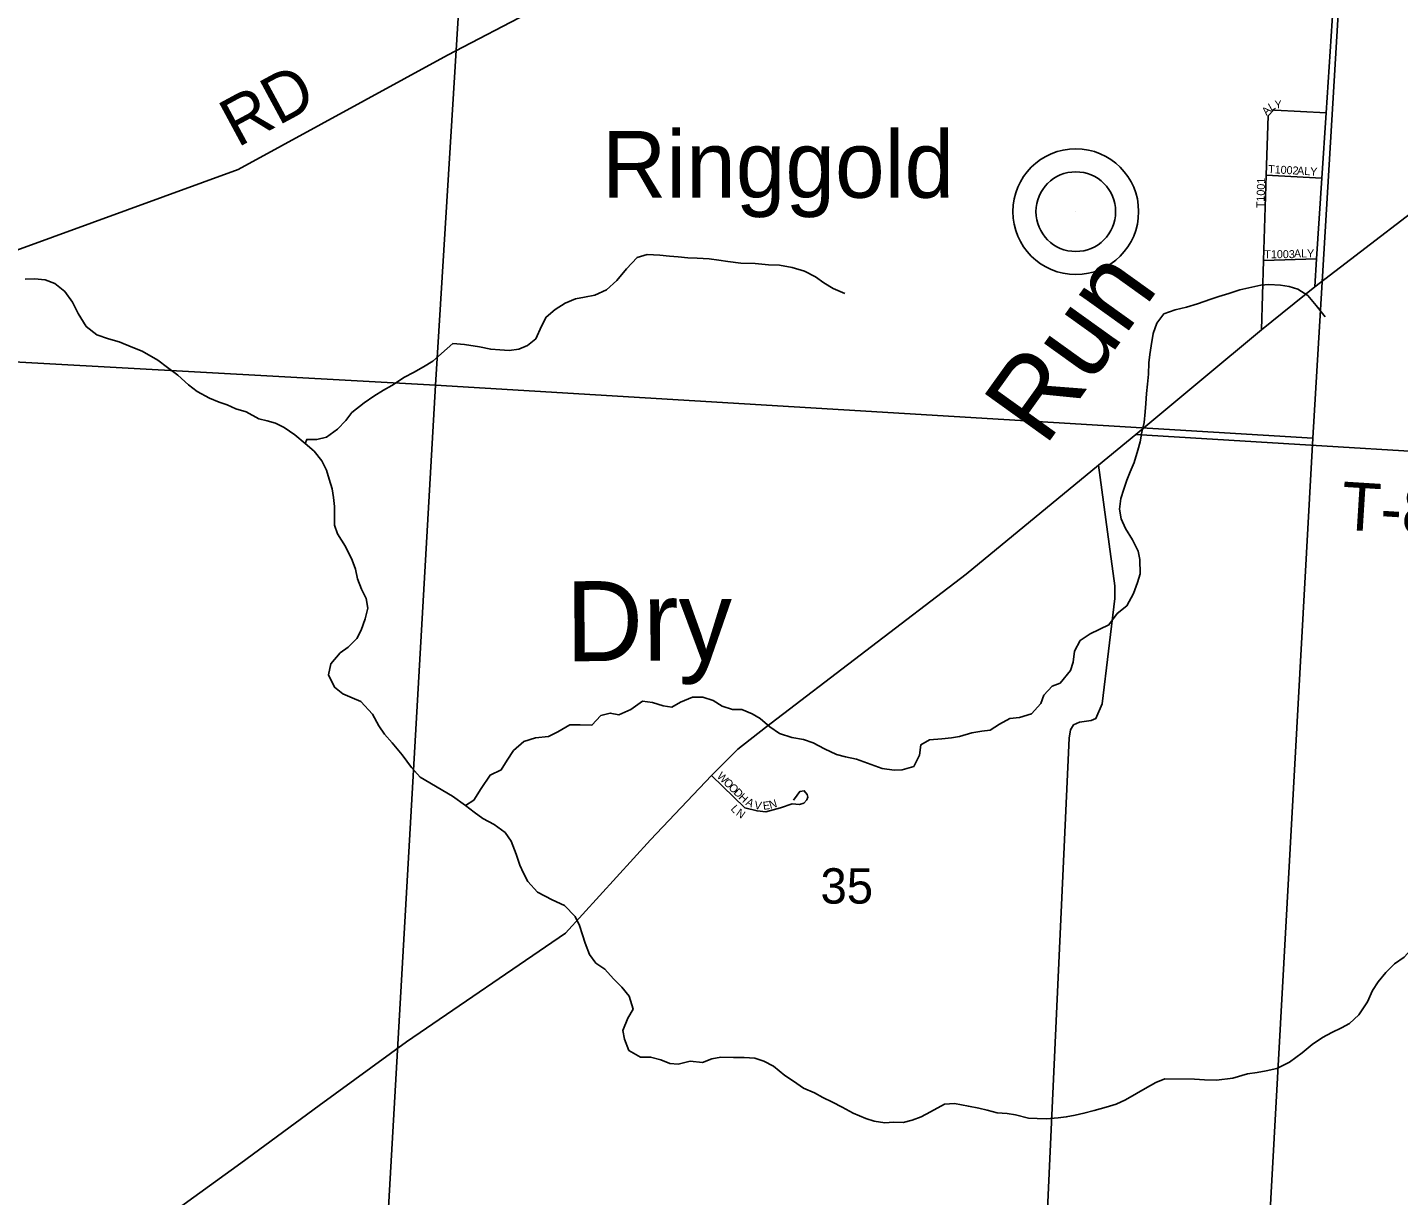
# Model space of a CAD drawing. Extents: x 1643459 to 2064572, y 425441 to 780708.
# Drawn here: x 1860299 to 1868868, y 602101 to 609399 of the extents above; entities that cross this region are included whole.
import ezdxf

# ---------------------------------------------------------------- set-up
doc = ezdxf.new("R2010")
doc.units = 0
for name, color, linetype in [('GE_P_Alignment_100_Curve_Data', 7, 'Continuous'), ('GM_X_Adjacent_County', 7, 'Continuous'), ('GM_X_County', 7, 'Continuous'), ('GM_X_Interchange_Ramps', 7, 'Continuous'), ('GM_X_Major_River', 7, 'Continuous'), ('GM_X_Major_River_Text', 7, 'Continuous'), ('GM_X_Minor_Lake', 7, 'Continuous'), ('GM_X_Rail_Line', 7, 'Continuous'), ('GM_X_State_Route', 7, 'Continuous'), ('GM_X_Township', 7, 'Continuous'), ('GM_X_Township_ROW', 7, 'Continuous'), ('GM_X_US_Route', 7, 'Continuous'), ('RD_X_Text', 7, 'Continuous')]:
    doc.layers.add(name, color=color, linetype=linetype)

msp = doc.modelspace()

# ---------------------------------------------------------------- linework, layer by layer
at = {"layer": 'GE_P_Alignment_100_Curve_Data'}
for radius in [392.8, 249]:
    msp.add_circle((1866850.6, 608248.3), radius, dxfattribs=at)
at = {"layer": 'GM_X_County'}
for points in [[(1868094, 608883.3), (1868093.8, 608883.4), (1868088.5, 608883.7), (1868052.2, 608847.9), (1868040.7, 608475.5), (1868024.2, 607942.7), (1868010.7, 607509)], [(1868415.4, 608866), (1868094, 608883.3)], [(1868040.7, 608475.5), (1868388.5, 608456.9)], [(1868024.2, 607942.7), (1868355.4, 607952.6)], [(1864574.9, 604724.7), (1864782.4, 604524.3), (1864859.2, 604503.9), (1864914.6, 604497.9), (1865004.6, 604523.2), (1865078.7, 604547.4), (1865124.7, 604544.9), (1865150.4, 604552.1), (1865170, 604572.6), (1865176.1, 604589.1), (1865172, 604607.6), (1865153.7, 604630.6), (1865125.8, 604625.1), (1865109.3, 604603.5), (1865086.7, 604570.6)]]:
    msp.add_lwpolyline(points, dxfattribs=at)
at = {"layer": 'GM_X_Major_River_Text'}
for points in [[(1857415.1, 607413.1), (1859119.2, 607332.8), (1859191.3, 607345), (1859211.3, 607367.1), (1859237.4, 607377.2), (1859289.5, 607369.3), (1859347.6, 607363.4), (1859403.7, 607387.6), (1859599.9, 607494.4), (1859984.2, 607762.1), (1860060.3, 607832.5), (1860154.2, 607953.1), (1860232.3, 608007.5), (1861616.3, 608512.3), (1862924.5, 609225.1), (1864011.6, 609793.8), (1868459.3, 609535.8)], [(1867226, 606856.6), (1873104.9, 606497.9), (1873820.9, 606443.6)], [(1866649.2, 601470.4), (1866810.2, 604959.6), (1866818.6, 605011.6), (1866836.9, 605041.5), (1866874.9, 605059.3), (1866946.9, 605068.7), (1866977, 605082.5), (1867015.6, 605172.3), (1867094.5, 605830.7), (1867095.1, 605910.8), (1867059.1, 606171.5), (1866992.9, 606664.6)]]:
    msp.add_lwpolyline(points, dxfattribs=at)
at = {"layer": 'GM_X_Minor_Lake'}
msp.add_lwpolyline([(1868343.9, 607777.6), (1868355.4, 607952.6), (1868388.5, 608456.9), (1868415.4, 608866), (1868459.3, 609535.8), (1868815.5, 614963.8)], dxfattribs=at)
at = {"layer": 'GM_X_Rail_Line'}
msp.add_line((1866850.6, 608248.3), (1866850.6, 608248.3), dxfattribs=at)
at = {"layer": 'GM_X_State_Route'}
for points in [[(1863187, 612633.8), (1862848.1, 607163.8), (1857425.1, 607463.9), (1857716.6, 612877.1)], [(1868658.1, 612275), (1868331.4, 606833.8), (1862848.1, 607163.8), (1863187, 612633.8)], [(1857425.1, 607463.9), (1862848.1, 607163.8), (1862535.6, 601696.9), (1858202.7, 601981.9), (1857186.9, 602036.8)], [(1862848.1, 607163.8), (1868331.4, 606833.8), (1868030.6, 601366.5), (1863143.4, 601667.3), (1862535.6, 601696.9)]]:
    msp.add_lwpolyline(points, close=True, dxfattribs=at)
at = {"layer": 'GM_X_US_Route'}
for points in [[(1862957.3, 607425.1), (1863031.2, 607418.3), (1863125, 607403.4), (1863194.9, 607388.7), (1863250.8, 607384.2), (1863308.8, 607381.6), (1863370.8, 607389), (1863425, 607412.6), (1863475.4, 607454.2), (1863512.1, 607532.1), (1863540.7, 607590), (1863597.1, 607637.6), (1863659.4, 607677.1), (1863723.7, 607704.6), (1863779.8, 607714.1), (1863845.9, 607727.5), (1863918.1, 607758.9), (1863982.7, 607818.5), (1864043.3, 607890.1), (1864110, 607961.7), (1864172.1, 607981.1), (1864250.1, 607976.4), (1864312, 607969.8), (1864365.9, 607965.2), (1864425.9, 607960.7), (1864483.9, 607958.1), (1864559.8, 607953.4), (1864619.7, 607944.8), (1864675.6, 607936.2), (1864757.5, 607927.4), (1864847.4, 607924.5), (1864931.3, 607915.7), (1864999.3, 607913.1), (1865077.2, 607900.3), (1865154.9, 607875.5), (1865224.6, 607840.7), (1865276.2, 607804.1), (1865333.9, 607767.5), (1865407.6, 607736.7)], [(1860285.5, 607826.4), (1860343.7, 607828.2), (1860409.8, 607821.9), (1860469.9, 607799.5), (1860531.9, 607749.1), (1860579.8, 607682.6), (1860615.6, 607612.2), (1860665.4, 607531.8), (1860733.4, 607479.3), (1860805.5, 607452.9), (1860871.6, 607434.5), (1860957.7, 607400), (1861015.8, 607375.7), (1861113.9, 607321.1), (1861173.9, 607274.7), (1861237.9, 607226.2), (1861305.8, 607165.7), (1861359.8, 607125.3), (1861435.9, 607082.9), (1861498, 607058.5), (1861548.1, 607042.2), (1861602.1, 607015.9), (1861666.2, 606997.6), (1861744.3, 606953.1), (1861796.4, 606940.8), (1861848.5, 606926.5), (1861902.6, 606900.2), (1861970.6, 606853.8), (1862034.5, 606799.3), (1862090.5, 606750.9), (1862138.4, 606692.5), (1862168.2, 606632.2), (1862184, 606575.9), (1862203.8, 606515.6), (1862211.6, 606461.4), (1862217.4, 606405.2), (1862217.1, 606351), (1862218.9, 606288.8), (1862236.7, 606234.5), (1862286.5, 606156), (1862328.2, 606071.5), (1862348.1, 606015.3), (1862361.8, 605955), (1862387.6, 605888.7), (1862415.5, 605830.3), (1862425.2, 605770.1), (1862408.9, 605703.9), (1862384.5, 605633.8), (1862358.2, 605581.7), (1862303.7, 605527.8), (1862253.4, 605491.9), (1862194.9, 605423.9), (1862180.6, 605353.7), (1862218.3, 605277.3), (1862270.3, 605234.9), (1862328.4, 605210.6), (1862382.5, 605188.3), (1862456.4, 605107.7), (1862494.2, 605035.2), (1862530, 604982.9), (1862578, 604928.5), (1862641.8, 604854), (1862699.7, 604775.5), (1862753.6, 604715), (1862954.9, 604596.8)], [(1867542.2, 607652.1), (1867612.4, 607671.5), (1867694.6, 607700.8), (1867744.8, 607718.4), (1867807, 607737.9), (1867875.1, 607759.3), (1867933.2, 607772.8), (1868007.4, 607788.1), (1868057.4, 607793.7), (1868129.4, 607788.9), (1868183.3, 607780.4), (1868239.1, 607763.8), (1868300.7, 607725.1), (1868352.1, 607662.5), (1868409.4, 607591.7)], [(1863036.3, 604537.9), (1863088.6, 604571.5), (1863135.3, 604643.3), (1863190, 604727), (1863260.3, 604760.4), (1863296.9, 604822.2), (1863337.4, 604882), (1863401.9, 604937.6), (1863474.1, 604961), (1863556.2, 604968.2), (1863614.5, 604997.7), (1863688.8, 605041.2), (1863752.8, 605042.5), (1863826.8, 605039.8), (1863883.3, 605099.5), (1863941.5, 605115), (1863995.4, 605104.4), (1864069.6, 605137.8), (1864142.1, 605189.3), (1864206, 605180.6), (1864271.8, 605159.9), (1864325.7, 605153.4), (1864380, 605183), (1864454.3, 605214.4), (1864520.3, 605215.8), (1864584, 605193.1), (1864639.7, 605158.4), (1864705.5, 605137.8), (1864763.5, 605137.2), (1864827.2, 605110.5), (1864878.9, 605081.9), (1864938.4, 605029.2), (1865000, 604988.5), (1865075.8, 604963.7), (1865149.6, 604951), (1865209.4, 604930.4), (1865281, 604891.6), (1865354.7, 604856.8), (1865412.5, 604842.2), (1865480.4, 604827.5), (1865572.1, 604794.5), (1865639.8, 604769.8), (1865715.7, 604759), (1865765.7, 604760.6), (1865837.9, 604781.9), (1865874.5, 604851.8), (1865883.1, 604917.9), (1865937.4, 604947.5), (1866013.4, 604954.8), (1866073.5, 604960.2), (1866123.6, 604969.8), (1866201.7, 604991.1), (1866263.8, 605002.5), (1866315.9, 605008.1), (1866374.2, 605045.6), (1866438.5, 605081.1), (1866498.6, 605088.6), (1866574.7, 605109.9), (1866631.3, 605175.5), (1866651.8, 605227.5), (1866702.3, 605283.2), (1866752.5, 605302.8), (1866817.2, 605382.4), (1866833.7, 605434.4), (1866842.4, 605502.5), (1866878.9, 605568.3), (1866941.3, 605609.9), (1867057.8, 605666.9), (1867108.5, 605736.6), (1867168.9, 605786.2), (1867211.6, 605862), (1867236.3, 605932), (1867252.8, 605986), (1867251.6, 606074.3), (1867240.1, 606126.5), (1867204.7, 606197.1), (1867161.4, 606269.7), (1867134, 606330.1), (1867124.6, 606390.4), (1867133.2, 606456.5), (1867151.7, 606514.5), (1867170.2, 606570.5), (1867190.7, 606622.4), (1867215.2, 606680.4), (1867238, 606758.4), (1867252.4, 606810.4), (1867263, 606870.5), (1867277.6, 606930.5), (1867284.2, 606996.7), (1867288.7, 607048.8), (1867293.3, 607112.9), (1867299.8, 607171), (1867304.4, 607233.2), (1867307, 607303.3), (1867313.5, 607355.4), (1867322, 607409.5), (1867334.7, 607487.6), (1867357.3, 607551.6), (1867401.9, 607609.3), (1867472.1, 607634.8), (1867542.2, 607652.1)], [(1862034.5, 606799.3), (1862044.7, 606825.4), (1862106.9, 606825.1), (1862167.1, 606838.9), (1862237.6, 606888.7), (1862288, 606942.7), (1862326.3, 606992.7), (1862402.9, 607054.6), (1862463.2, 607094.5), (1862523.6, 607132.3), (1862575.9, 607162.2), (1862656.4, 607214.1), (1862710.7, 607243.9), (1862775.1, 607277.8), (1862833.4, 607313.6), (1862957.3, 607425.1)], [(1862954.9, 604596.8), (1863036.3, 604537.9), (1863089.9, 604497.3), (1863145.5, 604456.6), (1863215.2, 604419.9), (1863284.7, 604369), (1863322.2, 604314.5), (1863353.4, 604234), (1863376.8, 604165.6), (1863398.3, 604115.2), (1863425.8, 604062.8), (1863487.1, 603996), (1863578.7, 603949), (1863654.3, 603914.2), (1863721.7, 603845.4), (1863749.1, 603788.9), (1863768.6, 603730.6), (1863784.1, 603678.3), (1863811.4, 603607.8), (1863850.9, 603553.3), (1863906.5, 603514.7), (1863962, 603454), (1864013.5, 603403.3), (1864058.9, 603346.7), (1864084.2, 603266.2), (1864051.6, 603208.4), (1864020.9, 603132.5), (1864030.4, 603078.2), (1864057.8, 603007.8), (1864129.4, 602965), (1864193.4, 602966.3), (1864257.2, 602949.7), (1864312.9, 602925.1), (1864364.9, 602922.6), (1864441, 602939.9), (1864517, 602933.2), (1864575.1, 602954.7), (1864633.2, 602966.2), (1864711.2, 602963.4), (1864779.2, 602962.8), (1864845.1, 602960.1), (1864900.9, 602941.5), (1864960.6, 602908.9), (1865032.1, 602852), (1865085.7, 602815.4), (1865149.3, 602772.7), (1865217, 602742), (1865270.7, 602713.4), (1865330.4, 602684.7), (1865390.1, 602654.1), (1865459.8, 602615.3), (1865539.4, 602582.4), (1865591.3, 602565.9), (1865657.1, 602555.2), (1865711.2, 602558.7), (1865771.1, 602558.2), (1865827.3, 602571.7), (1865885.4, 602593.2), (1865943.7, 602624.7), (1866030.1, 602672), (1866092.2, 602675.4), (1866180, 602658.6), (1866243.9, 602647.9), (1866297.7, 602633.4), (1866359.6, 602618.7), (1866421.5, 602614.1), (1866473.4, 602605.6), (1866555.2, 602584.8), (1866609.2, 602582.3), (1866665.1, 602579.7), (1866741.2, 602587), (1866791.2, 602592.6), (1866847.3, 602604.1), (1866901.4, 602615.6), (1866965.5, 602633), (1867039.7, 602652.4), (1867103.9, 602671.8), (1867162.1, 602699.3), (1867230.5, 602738.8), (1867284.7, 602770.4), (1867351.1, 602807.8), (1867407.3, 602829.4), (1867593.2, 602827.6), (1867655.1, 602823), (1867729.1, 602822.3), (1867833.2, 602835.3), (1867923.4, 602860.6), (1867983.5, 602870), (1868039.6, 602879.5), (1868107.7, 602894.9), (1868186, 602934.3), (1868264.6, 602991.7), (1868327, 603045.3), (1868393.4, 603088.8), (1868451.7, 603120.3), (1868512, 603149.8), (1868562.2, 603175.4), (1868620.7, 603231), (1868673.4, 603310.7), (1868704.1, 603382.7), (1868740.6, 603436.5)], [(1868740.6, 603436.5), (1868789.1, 603494.2), (1868843.6, 603547.8), (1868902, 603589.4), (1868962.6, 603657), (1869017.1, 603712.6), (1869099.7, 603776), (1869170.1, 603825.5), (1869220.4, 603853.1), (1869278.5, 603868.6), (1869356.4, 603865.8), (1869418.4, 603859.2), (1869476.3, 603850.7), (1869532.1, 603838.1), (1869620, 603823.2), (1869673.9, 603812.7), (1869725.8, 603806.2), (1869789.7, 603801.5), (1869853.7, 603802.9), (1869915.8, 603808.4)]]:
    msp.add_lwpolyline(points, dxfattribs=at)
at = {"layer": 'RD_X_Text'}
for points in [[(1867639, 607200), (1868010.7, 607509), (1868343.9, 607777.6), (1869262.4, 608483.3), (1869694.5, 608813.9), (1869829.6, 608914.4), (1870139.2, 609025.8), (1870147.6, 609028.7)], [(1867109.4, 606760.6), (1867226, 606856.6), (1867639, 607200)], [(1859936, 601036.1), (1860478.6, 601444), (1860985.5, 601834), (1861633.4, 602303.4), (1862122.2, 602664.6), (1862667.4, 603061.5), (1863662.1, 603740.7), (1864192.5, 604323.8), (1864574.9, 604724.7), (1864739.3, 604889.2), (1864912, 605024.8), (1866165, 605982.5), (1866992.9, 606664.6), (1867109.4, 606760.6), (1867109.4, 606760.6)]]:
    msp.add_lwpolyline(points, dxfattribs=at)

# ---------------------------------------------------------------- texts
at = {"layer": 'GM_X_Adjacent_County'}
msp.add_text('35', height=221, rotation=0.00001, dxfattribs=at).set_placement((1865255.2, 603924.9))
at = {"layer": 'GM_X_Interchange_Ramps'}
for s, height, rotation, p in [('Run', 500, 54.34698, (1866657.6, 606773.8)), ('Dry', 499.98, 0.34594, (1863664.6, 605438.9))]:
    msp.add_text(s, height=height, rotation=rotation, dxfattribs=at).set_placement(p)
at = {"layer": 'GM_X_Major_River'}
for s, rotation, p in [('RD', 28.33409, (1861611, 608646.2)), ('T-83', 356.44505, (1868503.1, 606262.7))]:
    msp.add_text(s, height=300, rotation=rotation, dxfattribs=at).set_placement(p)
at = {"layer": 'GM_X_Township'}
for s, rotation, p in [('Y', 4.63841, (1868096.1, 608891.3)), ('A', 46.15905, (1868043.4, 608846.5)), ('L', 29.16872, (1868070.7, 608875.8)), ('T1002', 356.82185, (1868051.9, 608490)), ('ALY', 356.05688, (1868232.4, 608481.2)), ('T1001', 88.40986, (1868028.9, 608269.8)), ('T1003', 0.00001, (1868029.4, 607957.7)), ('ALY', 0.00001, (1868214.2, 607962.1)), ('W', 315.68942, (1864604.1, 604716.5)), ('O', 315.69982, (1864645.1, 604676.5)), ('O', 315.69982, (1864676.6, 604645.8)), ('D', 315.69982, (1864708.1, 604615.1)), ('H', 315.6955, (1864739.6, 604584.3)), ('A', 332.55869, (1864784, 604544.2)), ('V', 350.17163, (1864838.9, 604518.6)), ('E', 6.94758, (1864898.2, 604510.7)), ('N', 16.02744, (1864941.6, 604516.7)), ('L', 312.77736, (1864690.6, 604514.3)), ('N', 325.08869, (1864723.2, 604480.9))]:
    msp.add_text(s, height=50, rotation=rotation, dxfattribs=at).set_placement(p)
at = {"layer": 'GM_X_Township_ROW'}
msp.add_text('Ringgold', height=417, rotation=0.00001, dxfattribs=at).set_placement((1863889, 608335.4))

doc.saveas('drawing.dxf')
